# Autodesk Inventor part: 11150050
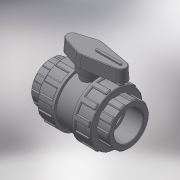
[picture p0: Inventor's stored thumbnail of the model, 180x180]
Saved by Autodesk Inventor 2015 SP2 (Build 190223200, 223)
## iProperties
Created: 2017-11
Part Number: 11150050
Material: Generic
Description: PLASSON 2/NUT VALVE CEM. PVC 50
Document SubType Name: Modeling
Designer: KIM
Density: 1 g/cm^3
Appearance: Default
Author: KIM
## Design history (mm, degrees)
derived "111500.ipt"
feature "Solid1::111500.ipt"
tag "TaggingFeature1"
body "Solid1"
other parameters: "d0" = 142, "d2" = 96, "d3" = 31, "d5" = 21.7, "d8" = 86.4, "d13" = 1.5, "d23" = 31, "d24" = 92.16, "d25" = 1, "d26" = 1.5, "d27" = 14.4, "d28" = 7.2, "d29" = 23.25, "d30" = 0, "d35" = 1.5, "d39" = 48, "d45" = 360 deg, "d47" = 1, "d50" = 52.8, "d51" = 28.8, "d53" = 0, "d56" = 5, "d57" = 21.7, "d58" = 0, "d59" = 1.5, "d61" = 360 deg, "d63" = 38.4, "d64" = 86, "d68" = 19.2, "d69" = 33, "d70" = 21.5, "d71" = 3 deg, "d73" = 1.92, "d74" = 44, "d75" = 2.58, "d76" = 0, "d77" = 1, "l_" = 31, "H_" = 142, "K_" = 96, "F_" = 86, "d67" = 38.4, "d72" = 9.6
